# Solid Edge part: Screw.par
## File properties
Title: Screw
Author: Robert a Rhodes jr
Template: Normal.par
Last saved by: CADCIM
Revision: 7
Application: Solid Edge
Material: aluminum
Accuracy: 0.99
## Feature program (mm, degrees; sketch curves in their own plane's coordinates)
sketch for "unnamed Protrusion 1" plane through (0, 0, 0) normal (0, -1, 0) x-axis (1, 0, 0)
  circle centre (0, 0) radius 12.5
extrude "unnamed Protrusion 1" add finite 25 along +normal
sketch for "ExtrudedProtrusion_2" plane through (0, -25, 0) normal (0, -1, 0) x-axis (1, 0, 0)
  circle centre (0, 0) radius 10
extrude "ExtrudedProtrusion_2" add finite 96 along +normal
sketch for "ExtrudedProtrusion_3" plane through (0, -121, 0) normal (0, -1, 0) x-axis (1, 0, 0)
  circle centre (0, 0) radius 6
extrude "ExtrudedProtrusion_3" add finite 4 along +normal
sketch for "ExtrudedProtrusion_4" plane through (0, -125, 0) normal (0, -1, 0) x-axis (1, 0, 0)
  circle centre (0, 0) radius 4
extrude "ExtrudedProtrusion_4" add finite 6 along +normal
sketch for "unnamed RevolvedProtrusion 1" plane through (0, 0, 0) normal (0, 0, 1) x-axis (1, 0, 0)
  line (0, -131) -> (6, -131)
  line (6, -131) -> (6, -141)
  line (6, -141) -> (0, -143.8522)
  line (0, -143.8522) -> (0, -131)
revolve "unnamed RevolvedProtrusion 1" add full turn 360 deg about sketch line (0, -131) -> (0, -106.3065)
sketch for "ExtrudedCutout_1" plane through (0, 0, 0) normal (1, 0, 0) x-axis (0, 1, 0)
  circle centre (-13, 0) radius 5.5
extrude "ExtrudedCutout_1" cut finite 222.1 symmetric
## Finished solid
Body 1: solid body, 12 faces, 12 edges, 1 vertex.
  Faces by surface: cylinder 6, plane 5, cone 1
  Edges by curve: circle 10, intersection 2
Bounding box of the edges (mm): 25.000 x 141.000 x 25.000, from (-12.5, -141, -12.5) to (12.5, 0, 12.5).
Cylindrical faces by radius (mm): R4 x1, R5.5 x1, R6 x2, R10 x1, R12.5 x1
Conical faces (half-angle, radius in mm at the cone's reference point): 64.5754 deg R6 x1
Planar faces by outward normal: +y 2, -y 3
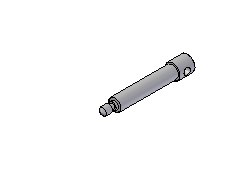
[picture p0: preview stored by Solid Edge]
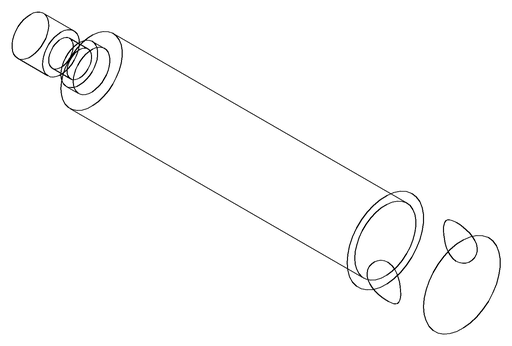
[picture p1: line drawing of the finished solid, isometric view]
